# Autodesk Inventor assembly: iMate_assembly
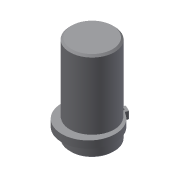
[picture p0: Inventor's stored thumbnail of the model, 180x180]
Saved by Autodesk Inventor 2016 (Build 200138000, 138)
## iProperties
Created: 2008-06
Part Number: iMate_assembly
Document SubType Name: Assembly
Designer: CADCIM
Author: CADCIM
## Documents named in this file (3)
- D:\KAVITA\Autodesk Inventor_ 2016 Project_Kavita\Inventor_Part Files\Inventor_2016_tut\c17_Inv_tut_2016\c17_tut02\iMate_assembly.iam
- D:\KAVITA\Autodesk Inventor_ 2016 Project_Kavita\Inventor_Part Files\Inventor_2016_tut\c17_Inv_tut_2016\c17_tut02\Shaft.ipt
- D:\KAVITA\Autodesk Inventor_ 2016 Project_Kavita\Inventor_Part Files\Inventor_2016_tut\c17_Inv_tut_2016\c17_tut02\circlip.ipt
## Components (2 placed, 2 different names)
1. Shaft:1
2. circlip:1
